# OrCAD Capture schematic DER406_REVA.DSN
size B
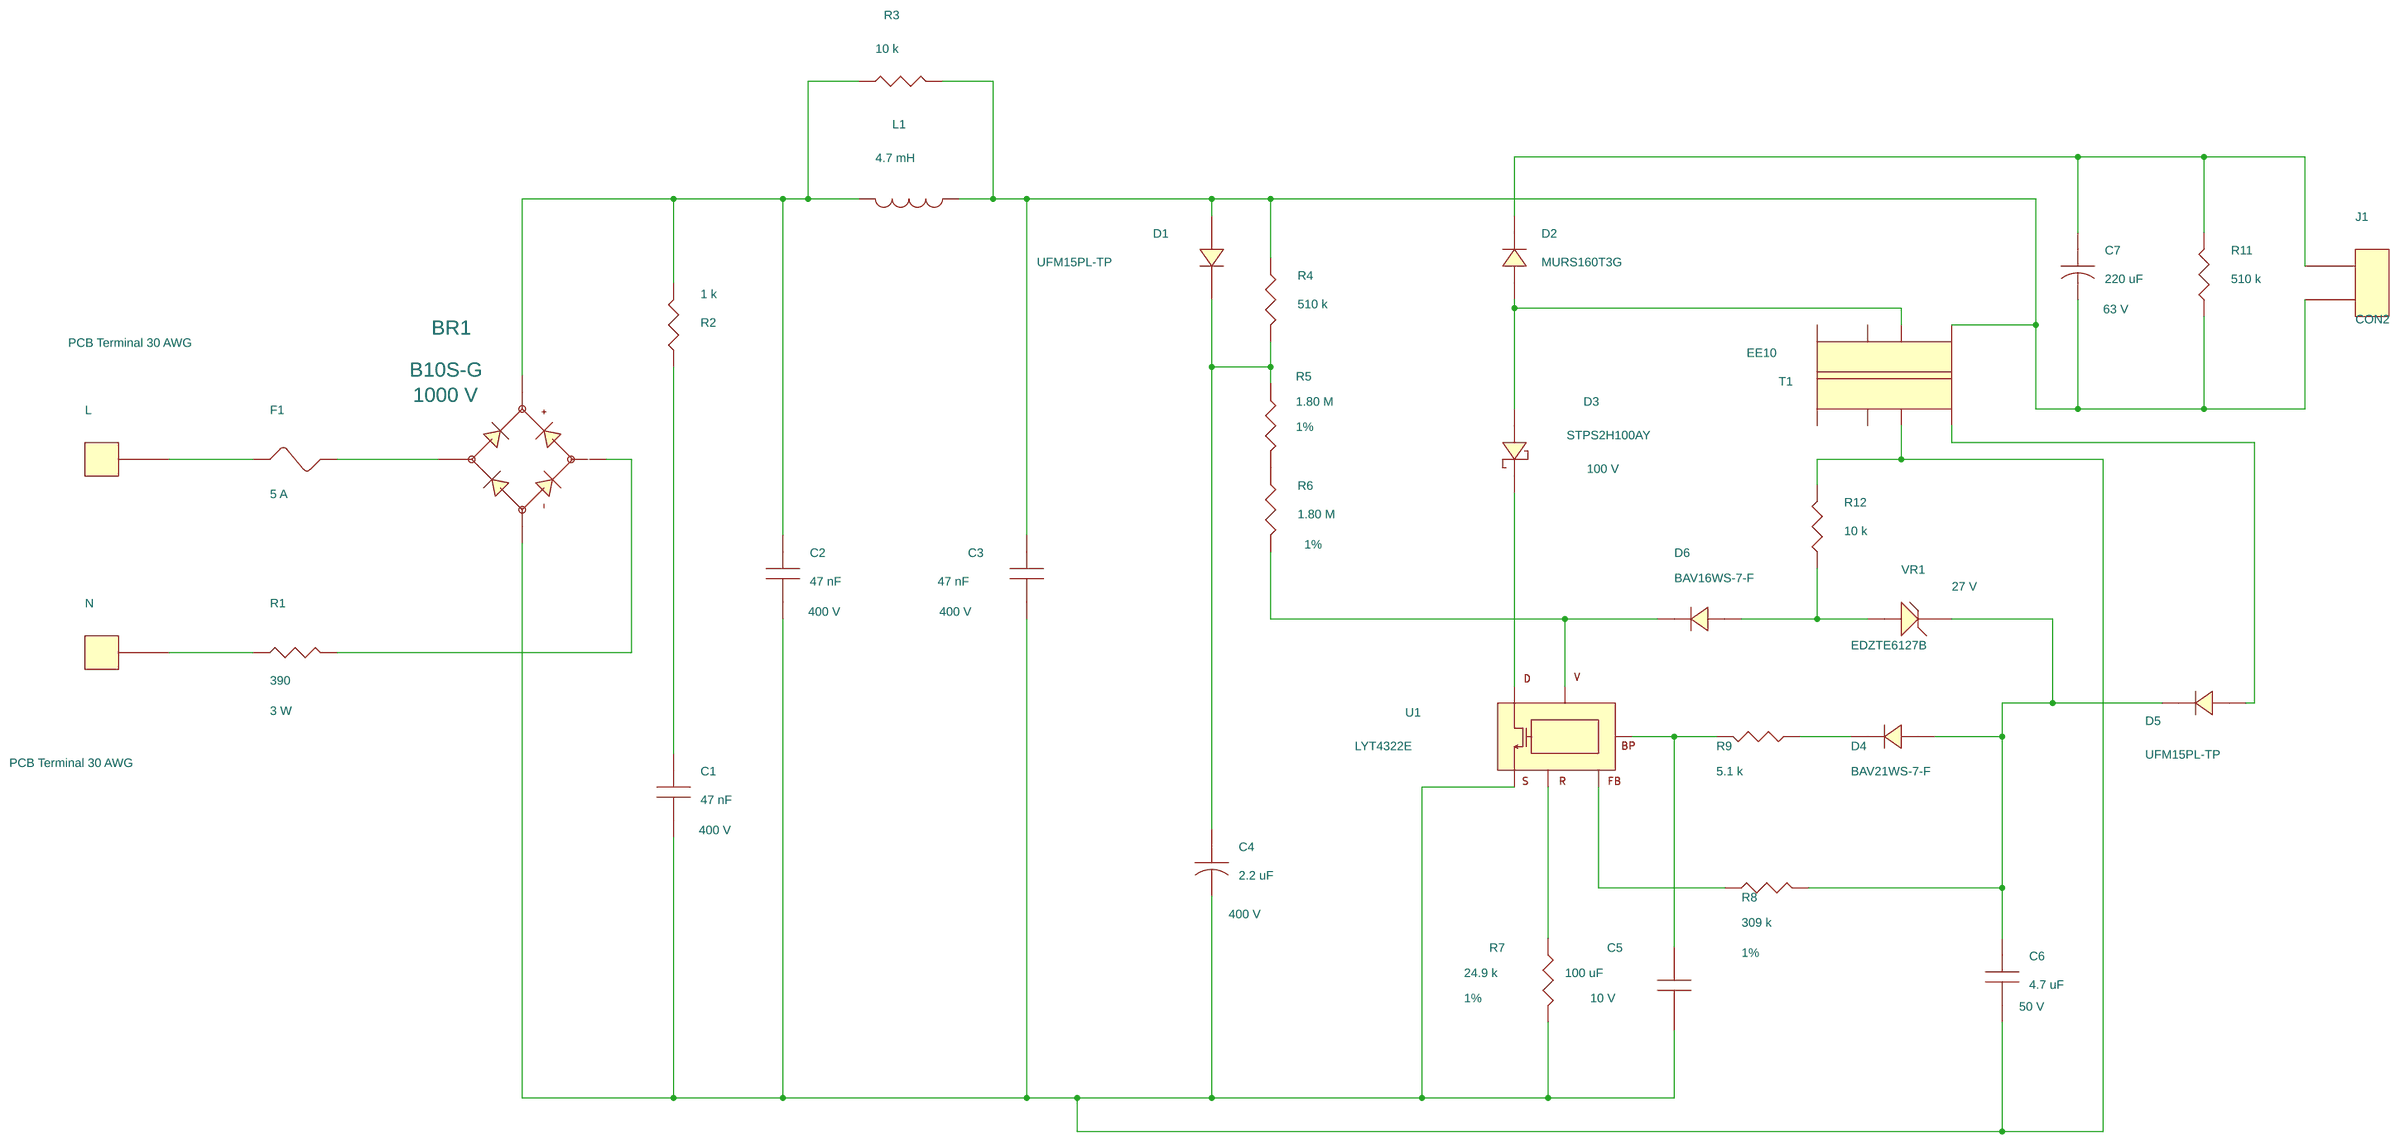
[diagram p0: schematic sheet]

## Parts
BR1  B10S-G  [pismsoic4]
C1  47 nF  [pinpcaprad500x240400040]
C2  47 nF  [pinpcaprad500x240400040]
C3  47 nF  [pinpcaprad500x240400040]
C4  2.2 uF  [pipolcapcyld250ls100030]
C5  100 uF  [pismc1206]
C6  4.7 uF  [pismc1206]
C7  220 uF  [pipolcapcyld400ls200040]
D1  UFM15PL-TP  [pi_sm_sod-123_12]
D2  MURS160T3G  [pismsmb]
D3  STPS2H100AY  [pismdsma]
D4  BAV21WS-7-F  [pismsod323]
D5  UFM15PL-TP  [pi_sm_sod-123_12]
D6  BAV16WS-7-F  [pismsod323]
F1  5 A  [pi_v_axial_160ls150d030]
J1  CON2  [pi_conn_lee_leds]
L  PCB Terminal 30 AWG  [pi_hole_30awg]
L1  4.7 mH  [pi12wvresd180ls150d040]
N  PCB Terminal 30 AWG  [pi_hole_30awg]
R1  390  [pi3wresd230ls775050]
R2  1 k  [pismr2512]
R3  10 k  [pismr0805]
R4  510 k  [pismr1206]
R5  1.80 M  [pismr1206]
R6  1.80 M  [pismr1206]
R7  24.9 k  [pismr0805]
R8  309 k  [pismr0603]
R9  5.1 k  [pismr1206]
R11  510 k  [pismr0805]
R12  10 k  [pismr0603]
T1  EE10  [pi_bobbin_ee10_8p]
U1  LYT4322E  [piicesip76th]
VR1  EDZTE6127B  [pismdsod52312]

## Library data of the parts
BR1 = DIODE_BRIDGE_~~+-: Disp_Voltage: 1000 V; Part Number: 15-00818-00; ROOM: 1
C1-C3 = CAP_NP: Disp_Voltage: 400 V; Part Number: 20-00365-00; Voltage: 400 V
C4 = CAP_POL: ALT_SYMBOLS: pipolcapcyld250ls100030h; Disp_Voltage: 400 V; Part Number: 20-01008-00; Voltage: 400 V
C5 = CAP_NP: Disp_Voltage: 10 V; Part Number: 20-01019-00; Voltage: 10 V
C6 = CAP_NP: Disp_Voltage: 50 V; Part Number: 20-08752-00; Voltage: 50 V
C7 = CAP_POL: ALT_SYMBOLS: pipolcapclyd395x630ls200030h; Disp_Voltage: 63 V; FPLIST: pipolcapcyld400ls200040,pipolcapclyd395x630ls200030h; Part Number: 20-01118-00; Voltage: 63 V
D1 D5 = DIODE: Part Number: 15-00927-00
D2 = DIODE: Part Number: 15-00487-00
D3 = DIODE_SCHOTTKY: Disp_Voltage: 100 V; Part Number: 15-00985-00
D4 = DIODE: Part Number: 15-00385-00
D6 = DIODE: Part Number: 15-00850-00
F1 = FUSE: FPLIST: pi_v_axial_160ls150d030,pi_v_axial_160ls250d030,pi12wvresd180ls200d040; Part Number: 40-00026-00
J1 = CON2: Part Number: 35-00252-00
L N = TERM_1Pin: Part Number: 35-00026-00
L1 = INDUCTOR: FPLIST: pi12wresd180ls675d040,pi12wvresd180ls150d040,pi12wvresd180ls200d040,pi12wvresd180ls250d040; Part Number: 30-00126-00; ROOM: 1
R1 = R: Disp_Power: 3 W; FPLIST: pi_3w_vres205ls200d040,pi3wresd230ls775050; Part Number: 05-03514-00
R2 = R: Part Number: 05-05366-00; ROOM: 1
R3 = R: Part Number: 05-01543-00; ROOM: 1
R4 = R: Part Number: 05-01417-00
R5 R6 = R: Disp_Tol: 1%; Part Number: 05-03155-00
R7 = R: Disp_Tol: 1%; Part Number: 05-00722-00
R8 = R: Disp_Tol: 1%; Part Number: 05-01221-00
R9 = R: Part Number: 05-01369-00
R11 = R: Part Number: 05-01584-00
R12 = R: Part Number: 05-01712-00
T1 = BEE16_8P_GENERIC: Part Number: 25-00877-00
U1 = LNK40X_eSIP: Part Number: 10-00730-00
VR1 = DIODE_ZENER: Disp_Voltage: 27 V; Part Number: 15-00974-00

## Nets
N1678526: BR1.4 C1.2 C2.2 C3.2 C4.2 C5.2 C6.2 R7.1 R12.2 T1.7 U1.5(S)
N2200496: C4.1 D1.1 R4.2 R5.1
N2492766: R7.2 U1.1(R)
N2493445: C3.1 C7.2 D1.2 J1.2 L1.1 R3.2 R4.1 R11.1 T1.1
N2536376: BR1.2 R1.2
N2538393: BR1.3 C2.1 L1.2 R2.2 R3.1
N3672068: C7.1 D2.1 J1.1 R11.2
N3708225: C6.1 D4.2 D5.1 R8.2 VR1.1
N3711440: D2.2 D3.2 T1.2
N3826642: C1.1 R2.1
N3864850: D5.2 T1.8
N3866232: C5.1 R9.2 U1.4(BP)
N3866262: D4.1 R9.1
N3867131: D3.1 U1.7(D)
N3867249: R8.1 U1.3(FB)
N3868462: D6.1 R6.2 U1.2(V)
N3869103: N.1 R1.1
N3869150: F1.1 L.1
N3869154: BR1.1 F1.2
N3875066: D6.2 R12.1 VR1.2
N3884504: R5.2 R6.1

Not connected (* = marked no-connect by the designer): T1 3 4 5 6
